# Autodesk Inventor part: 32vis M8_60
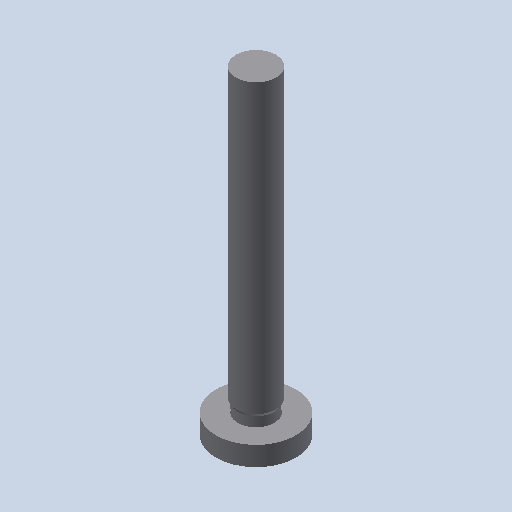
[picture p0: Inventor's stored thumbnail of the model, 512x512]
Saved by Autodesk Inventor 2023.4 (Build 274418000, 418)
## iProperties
Created: 2011-01
Part Number: 32vis M8_60
Document SubType Name: Modeling
Designer: eric
Density: 1 g/cm^3
Mass: 3.87317 g
Surface Area: 22.0249 cm^2
Volume: 3.87317 cm^3
Material: Générique
Appearance: Par défaut
Author: eric
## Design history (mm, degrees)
feature "Base1"
node "Corps solides"
node "Corps surfaciques"
node "Solide1"
